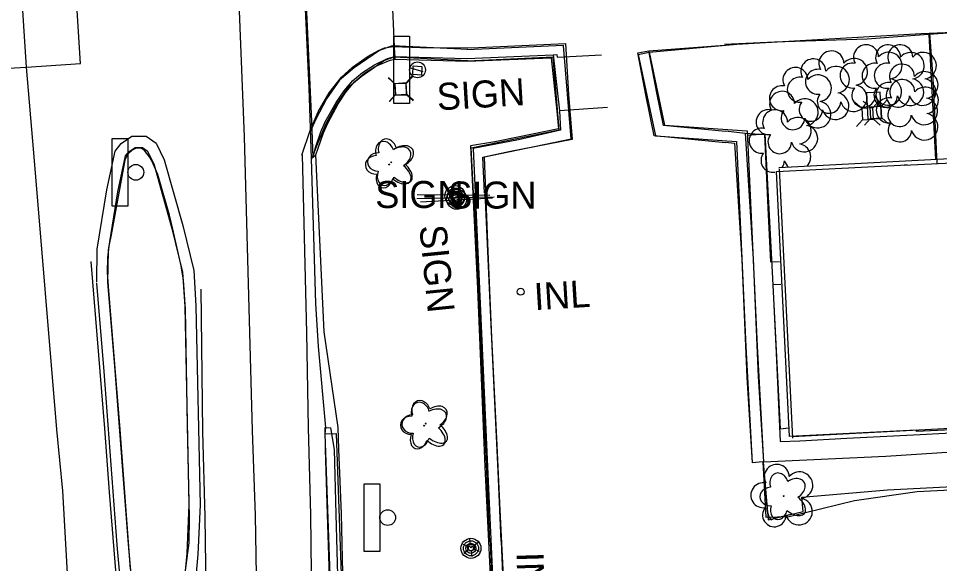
# Model space of a CAD drawing. Extents: x 588843 to 2552415, y 180129 to 269402.
# Drawn here: x 594716.2 to 594920.9, y 184465.5 to 184586.7 of the extents above; entities that cross this region are included whole.
import ezdxf

# ---------------------------------------------------------------- set-up
doc = ezdxf.new("R2010")
doc.units = 0
for name, color, linetype in [('Default', 7, 'Continuous'), ('E_BLD', 7, 'Continuous'), ('E_DRN', 7, 'Continuous'), ('E_DRN_Text', 7, 'Continuous'), ('E_DWY', 7, 'Continuous'), ('E_LAND_Vegetation', 7, 'Continuous'), ('E_LTG', 7, 'Continuous'), ('E_MISCPROP', 7, 'Continuous'), ('E_PATH_Sidewalk', 7, 'Continuous'), ('E_RDWY', 7, 'Continuous'), ('E_RDWY_AsphConc', 7, 'Continuous'), ('E_RDWY_C_and_G', 7, 'Continuous'), ('E_RDWY_PavtEdge', 7, 'Continuous'), ('E_SGN', 7, 'Continuous'), ('E_SGN_Text', 7, 'Continuous'), ('E_STRUCT_Joint', 7, 'Continuous'), ('E_UTL_AG_Bold', 7, 'Continuous'), ('Level 12', 7, 'Continuous'), ('Level 17', 7, 'Continuous'), ('Level 18', 7, 'Continuous'), ('Level 21', 7, 'Continuous')]:
    doc.layers.add(name, color=color, linetype=linetype)

# ---------------------------------------------------------------- blocks, each defined once
blk = doc.blocks.new('LPOL')
at = {"layer": 'Default'}
for p, q in [((-4, 0), (-1.5, 0)), ((-0.75, 1.3), (-2, 3.46)), ((0.75, 1.3), (2, 3.46)), ((1.5, 0), (4, 0)), ((-2, -3.46), (-0.75, -1.3)), ((2, -3.46), (0.75, -1.3))]:
    blk.add_line(p, q, dxfattribs=at)
for radius in [1.5, 1.5, 1.5, 0.125]:
    blk.add_circle((0, 0), radius, dxfattribs=at)
blk = doc.blocks.new('INLT_58')
at = {"layer": 'E_DRN_Text'}
blk.add_text('INL', height=12, dxfattribs=at).set_placement((-11.03, -6))
blk = doc.blocks.new('PED')
at = {"layer": 'Default'}
for p, q in [((-2.5, 2.5), (-5.33, 5.33)), ((2.5, 2.5), (5.33, 5.33)), ((-2.5, -2.5), (-5.33, -5.33)), ((2.5, -2.5), (5.33, -5.33))]:
    blk.add_line(p, q, dxfattribs=at)
blk.add_lwpolyline([(-2.5, -2.5), (2.5, -2.5), (2.5, 2.5), (-2.5, 2.5)], close=True, dxfattribs=at)
blk = doc.blocks.new('SGN_1')
at = {"layer": 'Default'}
blk.add_lwpolyline([(-3.5, -15), (-10.5, -15), (-10.5, 15), (-3.5, 15)], close=True, dxfattribs=at)
blk.add_circle((0, 0), 3.5, dxfattribs=at)
blk = doc.blocks.new('DTRE_1_1')
at = {"layer": 'Default'}
blk.add_circle((-0.18, 0), 0.183, dxfattribs=at)
for centre, major_axis, ratio in [((-1.87, 5.32), (1.36, -4.98), 0.782863), ((-5.87, 0.15), (4.93, -0.12), 0.832022), ((4.06, 2.74), (-5.27, -2.93), 0.691916), ((-2.49, -5.24), (1.8, 4.86), 0.716896), ((3.54, -3.71), (-5.01, 4.58), 0.560249)]:
    blk.add_ellipse(centre, major_axis=major_axis, ratio=ratio, start_param=1.570796, end_param=4.712389, dxfattribs=at)
blk = doc.blocks.new('BSGN_1')
at = {"layer": 'Default'}
blk.add_text('SIGN', height=12, dxfattribs=at).set_placement((-18.56, -6))
blk = doc.blocks.new('POLE_1_1')
at = {"layer": 'Default'}
for radius in [4.46, 3.35, 2.23, 1.12]:
    blk.add_circle((0, 0), radius, dxfattribs=at)
blk = doc.blocks.new('POLE_3')
at = {"layer": 'E_MISCPROP'}
for radius in [14.6, 11, 7.32, 3.66]:
    blk.add_circle((0, 0), radius, dxfattribs=at)
blk = doc.blocks.new('PED_3')
at = {"layer": 'E_UTL_AG_Bold'}
for p, q in [((-8.2, 8.2), (-17.5, 17.5)), ((8.2, 8.2), (17.5, 17.5)), ((-8.2, -8.2), (-17.5, -17.5)), ((8.2, -8.2), (17.5, -17.5))]:
    blk.add_line(p, q, dxfattribs=at)
blk.add_lwpolyline([(-8.2, -8.2), (8.2, -8.2), (8.2, 8.2), (-8.2, 8.2)], close=True, dxfattribs=at)
blk = doc.blocks.new('INLT_32_2')
at = {"layer": 'E_DRN_Text'}
blk.add_text('INL', height=39.37, dxfattribs=at).set_placement((-36.2, -19.7))
blk = doc.blocks.new('DTRE_4')
at = {"layer": 'E_LAND_Vegetation'}
blk.add_circle((-0.6, 0), 0.601, dxfattribs=at)
for centre, major_axis, ratio in [((-6.1, 17.5), (4.5, -16.3), 0.782863), ((-19.3, 0.5), (16.2, -0.4), 0.832022), ((13.3, 9), (-17.3, -9.6), 0.691916), ((-8.2, -17.2), (5.9, 15.9), 0.716896), ((11.6, -12.2), (-16.4, 15), 0.560249)]:
    blk.add_ellipse(centre, major_axis=major_axis, ratio=ratio, start_param=1.570796, end_param=4.712389, dxfattribs=at)
blk = doc.blocks.new('SIGN_3')
at = {"layer": 'E_SGN'}
blk.add_text('SIGN', height=39.37, dxfattribs=at).set_placement((-56.1, -19.7))

msp = doc.modelspace()

# ---------------------------------------------------------------- linework, layer by layer
at = {"layer": 'E_BLD'}
msp.add_line((594885.18, 184553.27), (594888.19, 184493.38), dxfattribs=at)
msp.add_lwpolyline([(594931.34, 184495.6), (594915.76, 184494.83), (594915.75, 184495.15), (594887.49, 184493.76), (594884.59, 184552.69), (594913.65, 184554.12), (594912.97, 184554.09), (594984.08, 184557.57), (595102.54, 184563.39), (595104.21, 184529.31), (595096.26, 184528.92), (595097.45, 184504.62), (594974.02, 184498.56), (594974.3, 184492.84), (594931.58, 184490.74)], close=True, dxfattribs=at)
at = {"layer": 'E_DRN'}
msp.add_circle((594827.76, 184525.94), 0.757, dxfattribs=at)
at = {"layer": 'E_DWY'}
for points in [[(594853.87, 184578.66), (594856.32, 184579.18), (594875.82, 184580.94), (594916.75, 184583.36), (594959.55, 184585.14), (594984.11, 184586.69)], [(594779.17, 184556.3), (594780.99, 184561.76), (594782.8, 184565.95), (594785.24, 184570.14), (594787.92, 184573.66), (594790.38, 184575.83), (594793.88, 184578.26), (594796.14, 184579.59), (594797.51, 184580.13), (594799.54, 184580.45), (594805.52, 184580.23), (594816.78, 184580.12), (594837.76, 184581.09), (594838.37, 184569.79), (594839.18, 184559.79), (594825.53, 184557.13), (594819.64, 184555.83), (594820.44, 184534.91), (594821.27, 184515.75), (594822.44, 184491.73), (594823.15, 184477.34), (594824.36, 184452.42)], [(594816.04, 184579.77), (594799.21, 184580.58), (594796.38, 184579.56), (594790.79, 184575.69), (594787.49, 184572.97), (594784.6, 184568.8), (594782.23, 184564.31), (594781, 184561.45)], [(594819.74, 184547.94), (594819.35, 184555.87), (594839, 184559.91), (594837.31, 184580.67), (594815.81, 184579.67)], [(594853.79, 184579.01), (594856.25, 184579.48), (594873.09, 184580.74)], [(594873.28, 184561.55), (594859.5, 184562.9), (594858.01, 184570.16), (594856.25, 184579.48)], [(594815.92, 184577.27), (594799.59, 184578.06), (594797.53, 184577.32), (594792.3, 184573.69), (594789.35, 184571.26), (594786.74, 184567.5), (594784.49, 184563.23), (594782.37, 184558.31), (594781.2, 184555.24)], [(594817.25, 184547.82), (594816.75, 184557.89), (594836.33, 184561.91), (594835.01, 184578.06), (594815.92, 184577.17)], [(594873.3, 184559.03), (594857.43, 184560.59), (594855.56, 184569.67), (594853.79, 184579.01)], [(594853.87, 184578.66), (594857.7, 184560.57), (594875.74, 184559.33), (594877.82, 184513.72), (594879.24, 184487.91)], [(594856.32, 184579.18), (594859.76, 184562.94), (594878.13, 184561.67), (594880.32, 184513.85), (594881.74, 184488.05)], [(594878.18, 184560.7), (594882, 184561.05), (594883.64, 184530.27), (594885.45, 184495.46), (594887.39, 184495.64)], [(594817.35, 184547.82), (594818.74, 184516.93), (594820.2, 184485.9), (594820.87, 184470.35)], [(594819.84, 184547.93), (594821.24, 184517.04), (594822.7, 184486.01), (594823.37, 184470.45)], [(594881.64, 184488.04), (594882.74, 184475.24), (594890.54, 184477.1), (594890.22, 184480.27), (594909.31, 184481.87), (594925.21, 184482.68)], [(594881.99, 184484.19), (594882.3, 184479.9), (594882.53, 184477.26), (594882.95, 184475.86), (594883.4, 184475.25), (594884.42, 184475.67), (594887.77, 184476.5)], [(594820.97, 184470.35), (594821.77, 184449.51), (594833.71, 184450.08), (594838.3, 184450.41), (594869.17, 184447.72)], [(594823.47, 184470.45), (594824.17, 184452.13), (594833.56, 184452.58), (594838.32, 184452.91), (594869.39, 184450.21)]]:
    msp.add_lwpolyline(points, dxfattribs=at)
at = {"layer": 'E_PATH_Sidewalk'}
msp.add_lwpolyline([(594918.65, 184583.44), (594919.33, 184573.41), (594920.28, 184554.44)], dxfattribs=at)
at = {"layer": 'E_RDWY'}
msp.add_lwpolyline([(594777.4, 184632.83), (594779.06, 184606.45), (594780.67, 184571.28), (594781.19, 184555.56), (594782.21, 184523.33), (594782.74, 184513.75), (594784.36, 184495.78), (594784.28, 184494.37)], dxfattribs=at)
at = {"layer": 'E_RDWY_AsphConc'}
for points in [[(594705.7, 184575.19), (594717.98, 184575.83), (594729.93, 184576.63), (594728.28, 184603.88), (594725.93, 184649.38), (594725.41, 184663.64)], [(594781.64, 184555.76), (594781.37, 184563.82), (594779.87, 184596.3), (594777.6, 184629.78), (594777.08, 184633.63)], [(594798.34, 184612.59), (594799.04, 184593.94), (594799.76, 184578.72), (594799.79, 184578.23)], [(594799.79, 184578.23), (594815.83, 184577.77), (594834.99, 184578.63)], [(594834.99, 184578.63), (594835.84, 184578.68), (594835.87, 184578.08), (594845.72, 184578.56)], [(594836.36, 184566.13), (594836.64, 184561.85), (594827.27, 184559.72), (594822.24, 184558.74), (594817.19, 184557.79), (594818.62, 184526.54), (594820.42, 184487), (594822.09, 184449.91), (594838.7, 184450.71), (594855.26, 184449.33)], [(594847.08, 184566.89), (594836.36, 184566.13)], [(594787.23, 184495.75), (594784.09, 184516.99), (594782.22, 184556.35)]]:
    msp.add_lwpolyline(points, dxfattribs=at)
msp.add_lwpolyline([(594803.9, 184576.16), (594805.77, 184576.03), (594805.71, 184574.07), (594803.77, 184574.21)], close=True, dxfattribs=at)
at = {"layer": 'E_RDWY_C_and_G'}
for points in [[(594781.64, 184555.76), (594782.2, 184557.99), (594783.35, 184561.51), (594783.35, 184561.51), (594784.33, 184563.69), (594784.33, 184563.69), (594786.77, 184568.01), (594786.77, 184568.01), (594788.51, 184570.58), (594788.51, 184570.58), (594790.43, 184572.78), (594792.65, 184574.68), (594792.65, 184574.68), (594795.31, 184576.4), (594798.17, 184577.76), (594798.17, 184577.76), (594798.67, 184577.93), (594798.67, 184577.93), (594799.79, 184578.23), (594799.79, 184578.23)], [(594781.64, 184555.76), (594782.22, 184556.35), (594782.76, 184557.84), (594783.94, 184561.27), (594783.94, 184561.27), (594784.9, 184563.43), (594784.9, 184563.43), (594787.23, 184567.67), (594787.23, 184567.67), (594788.95, 184570.33), (594788.95, 184570.33), (594790.84, 184572.59), (594793.07, 184574.53), (594793.07, 184574.53), (594795.61, 184576.11), (594798.36, 184577.28), (594798.36, 184577.28), (594798.82, 184577.41), (594798.82, 184577.41), (594799.84, 184577.61), (594799.84, 184577.61)], [(594799.79, 184578.23), (594799.84, 184577.61), (594815.97, 184577.21), (594834.54, 184577.96), (594835.78, 184566.08), (594836.14, 184562.15), (594827.17, 184560.27), (594822.01, 184559.25), (594816.63, 184558.36), (594818.16, 184526.58), (594819.84, 184487.03), (594821.63, 184449.35), (594838.59, 184450.08), (594855.21, 184448.77)], [(594834.99, 184578.63), (594836.36, 184566.13)], [(594733.56, 184528.04), (594733.67, 184535.42), (594735.81, 184548.59), (594737.65, 184557.21), (594738.97, 184558.91), (594741.36, 184560.53), (594744.55, 184560.53), (594746.75, 184558.94), (594748.58, 184555.24), (594752.69, 184540.63), (594755.12, 184530.63), (594755.6, 184522.82)], [(594753.29, 184463.98), (594754.08, 184470.09), (594754.08, 184470.09), (594754.2, 184475.73), (594754.2, 184475.73), (594753.71, 184496.11), (594753.29, 184522.02), (594752.84, 184528.51), (594752.84, 184528.51), (594752.32, 184531.72), (594752.32, 184531.72), (594750.49, 184539.85), (594750.49, 184539.85), (594749.72, 184542.96), (594749.72, 184542.96), (594747.12, 184552), (594747.12, 184552), (594746.13, 184554.39), (594746.13, 184554.39), (594745.76, 184555.07), (594745.76, 184555.07), (594745.26, 184555.89), (594745.26, 184555.89), (594744.73, 184556.67), (594744.73, 184556.67), (594744.16, 184557.34), (594744.16, 184557.34), (594743.48, 184557.77), (594743.48, 184557.77), (594742.54, 184557.86), (594742.54, 184557.86), (594742.18, 184557.76), (594742.18, 184557.76), (594741.41, 184557.37), (594741.41, 184557.37), (594740.45, 184556.49), (594740.45, 184556.49), (594739.84, 184555.17), (594739.84, 184555.17), (594736.8, 184538.56), (594736.28, 184536.03), (594735.97, 184533.47), (594735.97, 184533.47), (594735.88, 184530.3), (594736.09, 184527.13), (594736.09, 184527.13), (594738.73, 184495.31), (594740.96, 184464.22)], [(594736.06, 184528), (594736.17, 184535.2), (594738.26, 184548.13), (594739.98, 184556.13), (594740.7, 184557.06), (594742.13, 184558.03), (594743.73, 184558.03), (594744.78, 184557.27), (594746.23, 184554.34), (594750.27, 184539.99), (594752.64, 184530.25), (594753.11, 184522.67)], [(594738.13, 184469.63), (594735.18, 184508.19), (594733.57, 184527.8)], [(594740.62, 184469.82), (594737.67, 184508.39), (594736.06, 184528)], [(594755.61, 184522.72), (594756.53, 184478.57), (594756.05, 184467.55), (594754.6, 184451.93), (594753.08, 184444.82), (594751.61, 184443.02), (594750.23, 184441.42), (594747.78, 184440.21), (594744.89, 184440.21), (594742.85, 184441.45), (594741.38, 184443.27), (594739.93, 184449.17), (594738.13, 184469.6)], [(594753.11, 184522.67), (594754.03, 184478.6), (594753.55, 184467.72), (594752.12, 184452.31), (594750.76, 184445.93), (594749.7, 184444.63), (594748.67, 184443.43), (594747.2, 184442.71), (594745.59, 184442.71), (594744.52, 184443.36), (594743.67, 184444.4), (594742.4, 184449.58), (594740.62, 184469.82)], [(594785.35, 184460.32), (594784.83, 184476.46), (594784.41, 184490.85), (594784.35, 184495.72), (594785.55, 184495.71)], [(594787.22, 184460.15), (594786.77, 184476.51), (594786.38, 184490.87), (594785.55, 184495.71)], [(594788.31, 184460.13), (594787.92, 184476.57), (594787.37, 184490.93), (594787.23, 184495.75)], [(594784.28, 184494.37), (594786.78, 184494.45), (594787.88, 184463.06), (594788.86, 184448.44), (594789.74, 184444.29), (594792.01, 184438.6), (594794.61, 184434.87), (594797.41, 184431.43)], [(594784.28, 184494.37), (594785.39, 184462.93), (594786.38, 184448.1), (594787.34, 184443.57), (594789.79, 184437.4), (594792.62, 184433.37), (594795.47, 184429.85)]]:
    msp.add_lwpolyline(points, dxfattribs=at)
at = {"layer": 'E_RDWY_PavtEdge'}
for points in [[(594769.3, 184449.63), (594768.81, 184476.19), (594768.17, 184495.11), (594766.41, 184560.33), (594764.46, 184608.96), (594761.88, 184651.59), (594759.18, 184701.67), (594756.97, 184752.3), (594753.92, 184805.39), (594753.11, 184816.97), (594752.39, 184828.97), (594751.91, 184840.99), (594751.91, 184840.99), (594751.86, 184846.91), (594752.06, 184852.84), (594752.06, 184852.84), (594753.49, 184875.84)], [(594727.23, 184460.71), (594726.02, 184481.69), (594724.71, 184495.31), (594719.61, 184556.84), (594717.98, 184575.83)], [(594781.42, 184450.56), (594781.14, 184476.35), (594780.63, 184495.65), (594780.25, 184516.82), (594779.26, 184556.36)], [(594739.38, 184444.79), (594736.37, 184481.37), (594735.33, 184495.5), (594732.29, 184532.64)], [(594758.01, 184448.98), (594757.67, 184475.89), (594757.13, 184494.89), (594756.77, 184526.47)]]:
    msp.add_lwpolyline(points, dxfattribs=at)
at = {"layer": 'E_SGN'}
for p, q in [((594806.1, 184574.81), (594803.07, 184575.67)), ((594805.48, 184545.89), (594821.51, 184546.82))]:
    msp.add_line(p, q, dxfattribs=at)
for points in [[(594804.66, 184546.66), (594821.88, 184547.02)], [(594804.75, 184547.54), (594820.94, 184547.42)]]:
    msp.add_lwpolyline(points, dxfattribs=at)
at = {"layer": 'E_STRUCT_Joint'}
msp.add_lwpolyline([(594717.98, 184575.83), (594716.09, 184604.5), (594713.91, 184646.35), (594712.03, 184682.26), (594711.16, 184698.07), (594708.52, 184750.44), (594706.01, 184804.37), (594704.93, 184820.12), (594704.22, 184835.88), (594704.22, 184835.88), (594704.12, 184844.28), (594704.38, 184852.67), (594704.38, 184852.67), (594706.06, 184880.73), (594706.06, 184880.73), (594708.17, 184909.35), (594708.17, 184909.35), (594709.15, 184918.19), (594710.66, 184926.95), (594710.66, 184926.95), (594714.29, 184943.4), (594718.44, 184959.72), (594718.44, 184959.72)], dxfattribs=at)
at = {"layer": 'Level 12'}
for points in [[(595103.37, 184564.96), (594885.16, 184553.5)], [(594888.17, 184493.75), (594931.68, 184496.04), (594931.95, 184490.86), (594975.12, 184493.12), (594974.87, 184497.91), (595097.42, 184504.34), (595096.15, 184528.53), (595105.26, 184529.01), (595103.37, 184564.96)]]:
    msp.add_lwpolyline(points, dxfattribs=at)
at = {"layer": 'Level 17'}
for points in [[(594922.71, 184583.38), (594918.47, 184583.09)], [(594918.47, 184583.09), (594918.36, 184583.09), (594904.77, 184582.07), (594884.2, 184581.42), (594873.09, 184580.87)], [(594918.47, 184583.09), (594919.98, 184555.33)], [(594873.27, 184561.68), (594877.66, 184561.15)], [(594877.66, 184561.15), (594879.41, 184533.26), (594880.52, 184507.05), (594881.7, 184488.08)], [(594877.66, 184561.15), (594881.93, 184560.86), (594882.71, 184544.57), (594883.25, 184532.57), (594885.31, 184532.65)], [(594873.3, 184559.16), (594875.3, 184558.92)], [(594875.3, 184558.92), (594876.91, 184533.13), (594878.02, 184506.92), (594879.2, 184487.93)], [(594885.58, 184527.53), (594883.83, 184527.44), (594884.51, 184512.32), (594885.46, 184492.65), (594889.8, 184492.8), (594900.27, 184493.38), (594916.56, 184494.2), (594931.73, 184494.99)], [(594881.7, 184488.08), (594908.94, 184489.38), (594928.21, 184490.65), (594928.34, 184486.9)], [(594881.6, 184488.08), (594879.2, 184487.93)], [(594881.7, 184488.08), (594881.6, 184488.08)], [(594881.6, 184488.08), (594882.22, 184475.83), (594887.46, 184475.97), (594901.97, 184479.52), (594915.88, 184481.51), (594924.74, 184481.94)]]:
    msp.add_lwpolyline(points, dxfattribs=at)
at = {"layer": 'Level 18'}
for centre, radius, start, end in [((594896.83, 184576.68), 2.78, 1.3946, 209.1675), ((594904.52, 184578.06), 2.78, 1.3946, 209.1675), ((594909.43, 184578.03), 2.78, 1.3946, 209.1675), ((594912.13, 184578.03), 2.78, 1.3946, 209.1675), ((594892.8, 184574.91), 2.78, 1.3946, 209.1675), ((594901.87, 184574.82), 2.97, 278.4237, 139.6575), ((594909.56, 184576.2), 2.97, 278.4237, 139.6575), ((594914.47, 184576.17), 2.97, 278.4237, 139.6575), ((594917.17, 184576.18), 2.97, 278.4237, 139.6575), ((594888.82, 184573.02), 2.78, 1.3946, 209.1675), ((594893.83, 184572.6), 2.78, 78.0716, 279.0826), ((594897.84, 184573.06), 2.97, 278.4237, 139.6575), ((594901.52, 184573.98), 2.78, 78.0716, 279.0826), ((594906.43, 184573.95), 2.78, 78.0716, 279.0826), ((594909.13, 184573.96), 2.78, 78.0716, 279.0826), ((594912.5, 184573.74), 2.78, 1.3946, 209.1675), ((594889.8, 184570.84), 2.78, 78.0716, 279.0826), ((594893.86, 184571.16), 2.97, 278.4237, 139.6575), ((594909.45, 184570.35), 2.97, 196.0745, 79.0477), ((594914.36, 184570.31), 2.97, 196.0745, 79.0477), ((594917.06, 184570.32), 2.97, 196.0745, 79.0477), ((594917.55, 184571.89), 2.97, 278.4237, 139.6575), ((594885.82, 184568.95), 2.78, 78.0716, 279.0826), ((594901.76, 184568.97), 2.97, 196.0745, 79.0477), ((594903.98, 184569.58), 2.61, 140.7797, 358.7123), ((594908.89, 184569.55), 2.61, 140.7797, 358.7123), ((594909.5, 184569.67), 2.78, 78.0716, 279.0826), ((594911.59, 184569.56), 2.61, 140.7797, 358.7123), ((594912.58, 184570.32), 2.78, 1.3946, 209.1675), ((594917.62, 184568.46), 2.97, 278.4237, 139.6575), ((594885.87, 184567.71), 2.78, 1.3946, 209.1675), ((594896.29, 184568.2), 2.61, 140.7797, 358.7123), ((594897.73, 184567.2), 2.97, 196.0745, 79.0477), ((594890.91, 184565.85), 2.97, 278.4237, 139.6575), ((594892.26, 184566.44), 2.61, 140.7797, 358.7123), ((594893.75, 184565.31), 2.97, 196.0745, 79.0477), ((594909.58, 184566.25), 2.78, 78.0716, 279.0826), ((594917.44, 184566.03), 2.97, 196.0745, 79.0477), ((594882.87, 184563.63), 2.78, 78.0716, 279.0826), ((594884.32, 184563.58), 2.78, 1.3946, 209.1675), ((594888.28, 184564.55), 2.61, 140.7797, 358.7123), ((594911.97, 184565.27), 2.61, 140.7797, 358.7123), ((594917.51, 184562.61), 2.97, 196.0745, 79.0477), ((594889.36, 184561.72), 2.97, 278.4237, 139.6575), ((594890.8, 184560), 2.97, 196.0745, 79.0477), ((594912.04, 184561.85), 2.61, 140.7797, 358.7123), ((594881.32, 184559.5), 2.78, 78.0716, 279.0826), ((594885.33, 184559.23), 2.61, 140.7797, 358.7123), ((594889.25, 184555.87), 2.97, 316.8734, 79.0477), ((594883.78, 184555.1), 2.61, 140.7797, 280.7444), ((594883.78, 184555.1), 2.61, 323.3262, 358.7123), ((594889.25, 184555.87), 2.97, 196.0745, 229.1342), ((594884.68, 184484.77), 2.78, 1.3946, 209.1675), ((594889.72, 184482.91), 2.97, 278.4237, 139.6575), ((594881.68, 184480.69), 2.78, 78.0716, 279.0826), ((594889.61, 184477.06), 2.97, 196.0745, 79.0477), ((594884.14, 184476.29), 2.61, 140.7797, 358.7123)]:
    msp.add_arc(centre, radius, start, end, dxfattribs=at)
at = {"layer": 'Level 21'}
msp.add_lwpolyline([(594904.6, 184570.13), (594904.9, 184564.29), (594907.93, 184564.44), (594907.63, 184570.28), (594904.6, 184570.13)], dxfattribs=at)

# ---------------------------------------------------------------- block references
at = {"layer": 'E_DRN_Text'}
for name, p, xscale, yscale, rotation in [('INLT_32_2', (594836.23, 184525.16), 0.15240030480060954, 0.15240030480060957, 3.4338469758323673), ('INLT_58', (594829.98, 184462.55), 0.49999999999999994, 0.5, -88.40702529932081)]:
    msp.add_blockref(name, p, dxfattribs=dict(at, xscale=xscale, yscale=yscale, rotation=rotation))
at = {"layer": 'E_LAND_Vegetation', "xscale": 0.15240030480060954, "yscale": 0.15240030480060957, "rotation": 3.4338469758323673}
for p in [(594798.66, 184554.23), (594806.75, 184496.62), (594886.31, 184480.51)]:
    msp.add_blockref('DTRE_4', p, dxfattribs=at)
at = {"layer": 'E_LAND_Vegetation', "xscale": 0.5, "yscale": 0.5}
for p in [(594799.11, 184554.69), (594806.44, 184496.15)]:
    msp.add_blockref('DTRE_1_1', p, dxfattribs=at)
at = {"layer": 'E_LTG', "xscale": 0.5, "yscale": 0.5, "rotation": -23.084058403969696}
msp.add_blockref('LPOL', (594816.73, 184469.05), dxfattribs=at)
at = {"layer": 'E_MISCPROP', "xscale": 0.5, "yscale": 0.5}
msp.add_blockref('POLE_1_1', (594813.17, 184547.28), dxfattribs=at)
at = {"layer": 'E_MISCPROP', "xscale": 0.15240030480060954, "yscale": 0.15240030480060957, "rotation": 3.4338469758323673}
for p in [(594813.54, 184546.5), (594816.72, 184468.89)]:
    msp.add_blockref('POLE_3', p, dxfattribs=at)
at = {"layer": 'E_SGN', "xscale": 0.5, "yscale": 0.5}
for name, p in [('SGN_1', (594804.85, 184575.26)), ('SGN_1', (594742.24, 184552.48)), ('BSGN_1', (594804.75, 184547.54)), ('BSGN_1', (594820.94, 184547.42)), ('SGN_1', (594798.21, 184475.72))]:
    msp.add_blockref(name, p, dxfattribs=at)
at = {"layer": 'E_SGN_Text'}
for p, xscale, yscale, rotation in [((594817.66, 184569.76), 0.15240030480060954, 0.15240030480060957, 3.4338469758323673), ((594809.07, 184532.31), 0.15240030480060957, 0.1524003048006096, -84.31519139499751)]:
    msp.add_blockref('SIGN_3', p, dxfattribs=dict(at, xscale=xscale, yscale=yscale, rotation=rotation))
at = {"layer": 'E_UTL_AG_Bold'}
for name, p, xscale, yscale, rotation in [('PED_3', (594801.12, 184571.01), 0.15240030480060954, 0.15240030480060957, 3.4338469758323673), ('PED', (594801.11, 184570.95), 0.49999999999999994, 0.5, -88.40702529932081), ('PED_3', (594904.87, 184565.46), 0.15240030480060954, 0.15240030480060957, 3.4338469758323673), ('PED_3', (594906.69, 184565.76), 0.15240030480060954, 0.15240030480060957, 3.4338469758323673)]:
    msp.add_blockref(name, p, dxfattribs=dict(at, xscale=xscale, yscale=yscale, rotation=rotation))

doc.saveas('drawing.dxf')
